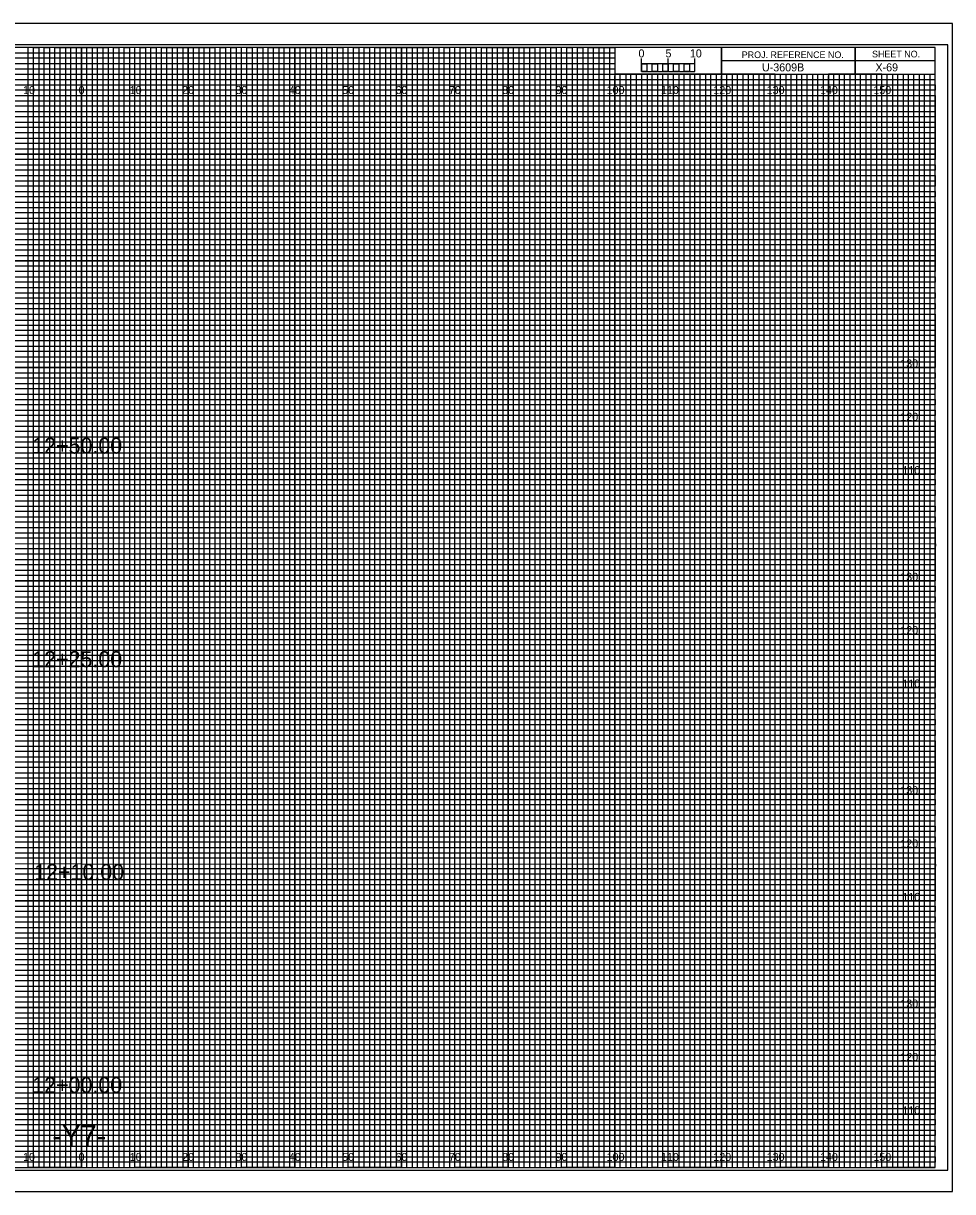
# Model space of a CAD drawing. Extents: x -13 to 323, y -5 to 215.
# Drawn here: x 149.1 to 323.3, y -4.5 to 214.5 of the extents above; entities that cross this region are included whole.
import ezdxf

# ---------------------------------------------------------------- set-up
doc = ezdxf.new("R2010")
doc.units = 0
for name, color, linetype in [('Prop XS Alignment Label', 7, 'Continuous'), ('Prop XS Bar Scale Labels', 7, 'Continuous'), ('Prop XS Elevation Labels', 7, 'Continuous'), ('Prop XS Offset Labels', 7, 'Continuous'), ('Prop XS Project Number', 7, 'Continuous'), ('Prop XS Sheet Number', 7, 'Continuous'), ('Prop XS Station Labels', 7, 'Continuous'), ('Sheet Cross Section CELL', 7, 'Continuous'), ('Sheet Cross Section Grid Major CELL', 7, 'Continuous'), ('Sheet Cross Section Grid Middle CELL', 7, 'Continuous'), ('Sheet Cross Section Grid Minor 1 CELL', 7, 'Continuous'), ('Sheet Cross Section Grid Minor 2 CELL', 7, 'Continuous'), ('Sheet Cross Section Scale CELL', 7, 'Continuous'), ('Sheet Cutting Line CELL', 7, 'Continuous'), ('Sheet DOT Grid CELL', 7, 'Continuous'), ('Sheet Plot Border Inside CELL', 7, 'Continuous'), ('Sheet Plot Border Outside CELL', 7, 'Continuous')]:
    doc.layers.add(name, color=color, linetype=linetype)

msp = doc.modelspace()

# ---------------------------------------------------------------- linework, layer by layer
at = {"layer": 'Sheet Cross Section CELL'}
for p, q in [((305, 210), (305, 205)), ((305, 205), (305, 210)), ((280, 207.5), (280, 205)), ((320, 207.49), (280, 207.49)), ((280, 205), (320, 205))]:
    msp.add_line(p, q, dxfattribs=at)
for points in [[(320, 210), (0, 210), (0, 0), (320, 0)], [(280, 210), (260, 210), (260, 205.03), (280, 205.03)], [(320, 210), (280, 210), (280, 205), (320, 205)]]:
    msp.add_lwpolyline(points, close=True, dxfattribs=at)
at = {"layer": 'Sheet Cross Section Grid Major CELL'}
for p, q in [((150, 210), (140, 210)), ((150, 0), (150, 210)), ((170, 210), (160, 210)), ((160, 210), (160, 0)), ((170, 0), (170, 210)), ((190, 210), (180, 210)), ((180, 210), (180, 0)), ((190, 0), (190, 210)), ((210, 210), (200, 210)), ((200, 210), (200, 0)), ((210, 0), (210, 210)), ((230, 210), (220, 210)), ((220, 210), (220, 0)), ((230, 0), (230, 210)), ((250, 210), (240, 210)), ((240, 210), (240, 0)), ((250, 0), (250, 210)), ((260, 210), (260, 0)), ((270, 0), (270, 205)), ((290, 205), (280, 205)), ((280, 205), (280, 0)), ((290, 0), (290, 205)), ((310, 205), (300, 205)), ((300, 205), (300, 0)), ((310, 0), (310, 205)), ((160, 0), (150, 0)), ((180, 0), (170, 0)), ((200, 0), (190, 0)), ((220, 0), (210, 0)), ((240, 0), (230, 0)), ((260, 0), (250, 0)), ((280, 0), (270, 0)), ((300, 0), (290, 0)), ((320, 0), (310, 0)), ((320, 0), (320, 0))]:
    msp.add_line(p, q, dxfattribs=at)
for points in [[(0, 200), (320, 200), (320, 190), (0, 190)], [(0, 180), (320, 180), (320, 170), (0, 170)], [(0, 160), (320, 160), (320, 150), (0, 150)], [(0, 140), (320, 140), (320, 130), (0, 130)], [(0, 120), (320, 120), (320, 110), (0, 110)], [(0, 100), (320, 100), (320, 90), (0, 90)], [(0, 80), (320, 80), (320, 70), (0, 70)], [(0, 60), (320, 60), (320, 50), (0, 50)], [(0, 40), (320, 40), (320, 30), (0, 30)], [(0, 20), (320, 20), (320, 10), (0, 10)]]:
    msp.add_lwpolyline(points, dxfattribs=at)
at = {"layer": 'Sheet Cross Section Grid Middle CELL'}
for points in [[(145, 0), (155, 0), (155, 210), (165, 210), (165, 0), (175, 0), (175, 210), (185, 210), (185, 0), (195, 0), (195, 210), (205, 210), (205, 0), (215, 0), (215, 210), (225, 210), (225, 0), (235, 0), (235, 210), (245, 210), (245, 0), (255, 0), (255, 210), (259.93, 210), (260, 210), (260, 205), (264.99, 205), (264.99, 0), (275, 0), (275, 205), (285, 205), (285, 0), (295, 0), (295, 205), (305, 205), (305, 0), (315, 0), (315, 205)], [(0, 205), (275, 205)], [(0, 185), (320, 185), (320, 195), (0, 195)], [(0, 165), (320, 165), (320, 175), (0, 175)], [(0, 145), (320, 145), (320, 155), (0, 155)], [(0, 125), (320, 125), (320, 135), (0, 135)], [(0, 105), (320, 105), (320, 115), (0, 115)], [(0, 85), (320, 85), (320, 95), (0, 95)], [(0, 65), (320, 65), (320, 75), (0, 75)], [(0, 45), (320, 45), (320, 55), (0, 55)], [(0, 25), (320, 25), (320, 35), (0, 35)], [(0, 5), (320, 5), (320, 15), (0, 15)]]:
    msp.add_lwpolyline(points, dxfattribs=at)
at = {"layer": 'Sheet Cross Section Grid Minor 1 CELL'}
for p, q in [((0, 209), (260, 209)), ((260, 209), (260, 207.98)), ((260, 207.98), (0, 207.98)), ((0, 207), (260, 207)), ((260, 205.89), (0, 205.89)), ((260, 207), (260, 205.89)), ((0, 204), (320, 204))]:
    msp.add_line(p, q, dxfattribs=at)
for points in [[(0, 203), (270, 203), (320, 203), (320, 202), (0, 202)], [(0, 201), (320, 201), (320, 199), (0, 199)], [(0, 198), (320, 198), (320, 197), (0, 196.98)], [(0, 196), (320, 196), (320, 194), (0, 194)], [(0, 193), (320, 193), (320, 192), (0, 192)], [(0, 191), (320, 191), (320, 189), (0, 189)], [(0, 188), (320, 188), (320, 187), (0, 187)], [(0, 186), (320, 186), (320, 184), (0, 184)], [(0, 183), (320, 183), (320, 182), (0, 182)], [(0, 181), (320, 181), (320, 179), (0, 179)], [(0, 178), (320, 178), (320, 177), (0, 177)], [(0, 176), (320, 176), (320, 173.95), (320, 173), (320, 172), (0, 172)], [(0, 174), (320, 174), (320, 173), (0, 173)], [(0, 171), (320, 171), (320, 169), (0, 169.03)], [(0, 169.03), (320, 169), (320, 168), (0, 168)], [(0, 167), (320, 167), (320, 166), (0, 166)], [(0, 164), (320, 164), (320, 163), (0, 163)], [(0, 162), (320, 162), (320, 161), (0, 161)], [(-0.07, 158.89), (320, 158.89), (320, 157.88), (-0.07, 157.88)], [(0, 157), (320, 157), (320, 156), (0, 156)], [(0, 154), (320, 154), (320, 153), (0, 153)], [(0, 152), (320, 152), (320, 151), (0, 151)], [(0, 149), (320, 149), (320, 148), (0, 148)], [(0, 147), (320, 147), (320, 146), (0, 146)], [(0, 144), (320, 144), (320, 143), (0, 143)], [(0, 142), (320, 142), (320, 141), (0, 141)], [(0, 139), (320, 139), (319.99, 137.98), (0, 138)], [(0, 137), (320, 137), (320, 136), (0, 136)], [(0, 134), (320, 134), (320, 133), (0, 133)], [(0, 132), (320, 132), (320, 131), (0, 131)], [(0, 129), (320, 129), (320, 128), (0, 128)], [(0, 127), (320, 127), (320, 126), (0, 126)], [(0, 124), (320, 124), (320, 123), (0, 123)], [(0, 122), (320, 122), (320, 121), (0, 121)], [(0, 119), (320, 119), (320, 118), (0, 118)], [(0, 116.99), (320.07, 116.91), (320, 116), (0, 116)], [(0, 114), (320, 114), (320, 113), (0, 113)], [(0, 112), (320, 112), (320, 111), (0, 111)], [(0, 109), (320, 109), (320, 108), (0, 108)], [(0, 107), (320, 107), (320, 106), (0, 106)], [(0, 104), (320, 104), (320, 103), (0, 103)], [(0, 102), (320, 102), (320, 101), (0, 101)], [(0, 99), (320, 99), (320, 98), (0, 98)], [(0, 97), (320, 97), (320, 96), (0, 96)], [(0, 94), (320, 94), (320, 93), (0, 93)], [(0, 92), (320, 92), (320, 91), (0, 91)], [(0, 89), (320, 89), (320, 88), (0, 88)], [(0, 87), (320, 87), (320, 86), (0, 86)], [(0, 84), (320, 84), (320, 83), (0, 83)], [(0, 82), (320, 82), (320, 81), (0, 81)], [(0, 79), (320, 79), (319.99, 77.98), (0, 78)], [(0, 77), (320, 77), (320, 76), (0, 76)], [(0, 74), (320, 74), (320, 73), (0, 73)], [(0, 72), (320, 72), (320, 71), (0, 71)], [(0, 69), (320, 69), (320, 68), (0, 68)], [(0, 67), (320, 67), (320, 66), (0, 66)], [(0, 64), (320, 64), (320, 63), (0, 63)], [(0, 62), (320, 62), (320, 61), (0, 61)], [(0, 59), (320, 59), (320, 58), (0, 58)], [(0, 56.99), (320.07, 56.91), (320, 56), (0, 56)], [(0, 54), (320, 54), (320, 53), (0, 53)], [(0, 52), (320, 52), (320, 51), (0, 51)], [(0, 49), (320, 49), (320, 48), (0, 48)], [(0, 47), (320, 47), (320, 46), (0, 46)], [(0, 44), (320, 44), (320, 43), (0, 43)], [(0, 42), (320, 42), (320, 41), (0, 41)], [(0, 39), (320, 39), (320, 38), (0, 38)], [(0, 37), (320, 37), (320, 36), (0, 36)], [(0, 34), (320, 34), (320, 33), (0, 33)], [(0, 32), (320, 32), (320, 31), (0, 31)], [(0, 29), (320, 29), (320, 28), (0, 28)], [(0, 27), (320, 27), (320, 26), (0, 26)], [(0, 24), (320, 24), (320, 23), (0, 23)], [(0, 22), (320, 22), (320, 21), (0, 21)], [(0, 19), (320, 19), (320, 18), (0, 18)], [(0, 17), (320, 17), (320, 16), (0, 16)], [(0, 14), (320, 14), (320, 13), (0, 13)], [(0, 12), (320, 12), (320, 11), (0, 11)], [(0, 9), (320, 9), (320, 8), (0, 8)], [(0, 7), (320, 7), (320, 6), (0, 6)], [(0, 4), (320, 4), (320, 3), (0, 3)], [(0, 2), (320, 2), (320, 1), (0, 1)]]:
    msp.add_lwpolyline(points, dxfattribs=at)
at = {"layer": 'Sheet Cross Section Grid Minor 2 CELL'}
for p, q in [((267, 205), (266.01, 205)), ((266.01, 205), (266.01, 0)), ((267, 0), (267, 205)), ((269, 205), (268, 205)), ((268, 205), (268, 0)), ((269, 0), (269, 205)), ((266.01, 0), (265, 0)), ((268, 0), (267, 0))]:
    msp.add_line(p, q, dxfattribs=at)
for points in [[(150, 0), (151, 0), (151, 210), (152, 210), (152, 0)], [(152, 0), (153, 0), (153, 210), (154, 210), (154, 0)], [(155, 0), (156, 0), (156, 210), (157, 210), (157, 0)], [(157, 0), (158, 0), (158, 210), (159, 210), (159, 0)], [(160, 0), (161, 0), (161, 210), (162, 210), (162, 0)], [(162, 0), (163, 0), (163, 210), (164, 210), (164, 0)], [(165, 0), (166, 0), (166, 210), (167, 210), (167, 0)], [(167, 0), (168, 0), (168, 210), (169, 210), (169, 0)], [(170, 0), (171, 0), (171, 210), (172, 210), (172, 0)], [(172, 0), (173, 0), (173, 210), (174, 210), (174, 0)], [(175, 0), (176, 0), (176, 210), (177, 210), (177, 0)], [(177, 0), (178, 0), (178, 210), (179, 210), (179, 0)], [(180, 0), (181, 0), (181, 210), (182, 210), (182, 0)], [(182, 0), (183, 0), (183, 210), (184, 210), (184, 0)], [(185, 0), (186, 0), (186, 210), (187, 210), (187, 0)], [(187, 0), (188, 0), (188, 210), (189, 210), (189, 0)], [(190, 0), (191, 0), (191, 210), (192, 210), (192, 0)], [(192, 0), (193, 0), (193, 210), (194, 210), (194, 0)], [(195, 0), (196, 0), (196, 210), (197, 210), (197, 0)], [(197, 0), (198, 0), (198, 210), (199, 210), (199, 0)], [(200, 0), (201, 0), (201, 210), (202, 210), (202, 0)], [(202, 0), (203, 0), (203, 210), (204, 210), (204, 0)], [(205, 0), (206, 0), (206, 210), (207, 210), (207, 0)], [(207, 0), (208, 0), (208, 210), (209, 210), (209, 0)], [(210, 0), (211, 0), (211, 210), (212, 210), (212, 0)], [(212, 0), (213, 0), (213, 210), (214, 210), (214, 0)], [(215, 0), (216, 0), (216, 210), (217, 210), (217, 0)], [(217, 0), (218, 0), (218, 210), (219, 210), (219, 0)], [(220, 0), (221, 0), (221, 210), (222, 210), (222, 0)], [(222, 0), (223, 0), (223, 210), (224, 210), (224, 0)], [(225, 0), (226, 0), (226, 210), (227, 210), (227, 0)], [(227, 0), (228, 0), (228, 210), (229, 210), (229, 0)], [(230, 0), (231, 0), (231, 210), (232, 210), (232, 0)], [(232, 0), (233, 0), (233, 210), (234, 210), (234, 0)], [(235, 0), (236, 0), (236, 210), (237, 210), (237, 0)], [(237, 0), (238, 0), (238, 210), (239, 210), (239, 0)], [(240, 0), (241, 0), (241, 210), (242, 210), (242, 0)], [(242, 0), (243, 0), (243, 210), (244, 210), (244, 0)], [(245, 0), (246, 0), (246, 210), (247, 210), (247, 0)], [(247, 0), (248, 0), (248, 210), (249, 210), (249, 0)], [(250, 0), (251, 0), (251, 210), (252, 210), (252, 0)], [(252, 0), (253, 0), (253, 210), (254, 210), (254, 0)], [(255, 0), (256, 0), (256, 210), (257, 210), (257, 0)], [(257, 0), (258, 0), (258, 210), (259, 210), (259, 0)], [(260, 0), (261, 0), (261, 205), (262.02, 205), (262.02, 0)], [(262, 0), (263, 0), (263, 205), (263.99, 205), (263.99, 0)], [(270, 0), (270.98, 0), (270.98, 205), (272, 205), (272, 0)], [(272, 0), (273, 0), (273, 205), (274.05, 205), (274.05, 0)], [(275, 0), (276, 0), (276, 205), (277, 205), (277, 0)], [(277, 0), (278, 0), (278, 205), (279, 205), (279, 0)], [(280, 0), (281, 0), (281, 205), (282, 205), (282, 0)], [(282, 0), (283, 0), (283, 205), (284, 205), (284, 0)], [(285, 0), (286, 0), (286, 205), (287, 205), (287, 0)], [(287, 0), (288, 0), (288, 205), (289, 205), (289, 0)], [(290, 0), (291, 0), (291, 205), (292, 205), (292, 0)], [(292, 0), (293, 0), (293, 205), (294, 205), (294, 0)], [(295, 0), (296, 0), (296, 205), (297, 205), (297, 0)], [(297, 0), (298, 0), (298, 205), (299, 205), (299, 0)], [(300, 0), (301, 0), (301, 205), (302, 205), (302, 0)], [(302, 0), (303, 0), (303, 205), (304, 205), (304, 0)], [(305, 0), (306, 0), (306, 205), (307, 205), (307, 0)], [(307, 0), (308, 0), (308, 205), (309, 205), (309, 0)], [(310, 0), (311, 0), (311, 205), (312, 205), (312, 0)], [(312, 0), (313, 0), (313, 205), (314, 205), (314, 0)], [(315, 0), (316, 0), (316, 205), (317, 205), (317, 0)], [(317, 0), (318, 0), (318, 205), (319, 205), (319, 0)]]:
    msp.add_lwpolyline(points, dxfattribs=at)
at = {"layer": 'Sheet Cross Section Scale CELL'}
for p, q in [((265, 205.49), (265, 207.9)), ((265, 206.9), (265, 207.9)), ((270, 205.49), (270, 207.9)), ((275, 205.49), (275, 207.9)), ((275, 206.9), (275, 207.9))]:
    msp.add_line(p, q, dxfattribs=at)
for points in [[(275, 206.9), (265, 206.9), (265, 205.49), (275, 205.49)], [(265, 206.9), (266, 206.9), (266, 205.49), (265, 205.49)], [(267, 206.9), (268, 206.9), (268, 205.49), (267, 205.49)], [(269, 206.9), (270, 206.9), (270, 205.49), (269, 205.49)], [(271, 206.9), (272, 206.9), (272, 205.49), (271, 205.49)], [(273, 206.9), (274, 206.9), (274, 205.49), (273, 205.49)]]:
    msp.add_lwpolyline(points, close=True, dxfattribs=at)
at = {"layer": 'Sheet Cutting Line CELL'}
for p, q in [((323.3, 214.5), (-13.4, 214.5)), ((-13.4, -4.5), (323.3, -4.5))]:
    msp.add_line(p, q, dxfattribs=at)
at = {"layer": 'Sheet DOT Grid CELL'}
for p, q in [((150, 0), (150, 210)), ((160, 0), (160, 210)), ((170, 0), (170, 210)), ((180, 0), (180, 210)), ((190, 0), (190, 210)), ((200, 0), (200, 210)), ((210, 0), (210, 210)), ((220, 0), (220, 210)), ((230, 0), (230, 210)), ((240, 0), (240, 210)), ((250, 0), (250, 210)), ((260, 0), (260, 204.69)), ((270, 0), (270, 204.69)), ((280, 0), (280, 204.69)), ((290, 0), (290, 204.69)), ((300, 0), (300, 204.69)), ((310, 0), (310, 204.69)), ((0, 200), (320, 200)), ((0, 190), (320, 190)), ((0, 180), (320, 180)), ((0, 170), (320, 170)), ((0, 160), (320, 160)), ((0, 150), (320, 150)), ((0, 140), (320, 140)), ((0, 130), (320, 130)), ((0, 120), (320, 120)), ((0, 110), (320, 110)), ((0, 100), (320, 100)), ((0, 90), (320, 90)), ((0, 80), (320, 80)), ((0, 70), (320, 70)), ((0, 60), (320, 60)), ((0, 50), (320, 50)), ((0, 40), (320, 40)), ((0, 30), (320, 30)), ((0, 20), (320, 20)), ((0, 10), (320, 10))]:
    msp.add_line(p, q, dxfattribs=at)
at = {"layer": 'Sheet Plot Border Inside CELL'}
msp.add_lwpolyline([(-10.8, -0.5), (322.4, -0.5), (322.4, 210.5), (-10.8, 210.5)], close=True, dxfattribs=at)
at = {"layer": 'Sheet Plot Border Outside CELL'}
msp.add_lwpolyline([(-13.4, -4.5), (323.3, -4.5), (323.3, 214.5), (-13.4, 214.5)], close=True, dxfattribs=at)

# ---------------------------------------------------------------- texts
at = {"layer": 'Prop XS Alignment Label'}
msp.add_text('-Y7-', height=4, dxfattribs=at).set_placement((154.52, 4))
at = {"layer": 'Prop XS Bar Scale Labels'}
for s, p in [('5', (269.47, 208.12)), ('10', (274.04, 208.12))]:
    msp.add_text(s, height=1.5, dxfattribs=at).set_placement(p)
at = {"layer": 'Prop XS Elevation Labels'}
for s, p in [('130', (313.49, 150)), ('120', (313.5, 140)), ('110', (313.88, 130)), ('130', (313.49, 110)), ('120', (313.5, 100)), ('110', (313.88, 90)), ('130', (313.49, 70)), ('120', (313.5, 60)), ('110', (313.88, 50)), ('130', (313.49, 30)), ('120', (313.5, 20)), ('110', (313.88, 10))]:
    msp.add_text(s, height=1.5, dxfattribs=at).set_placement(p)
at = {"layer": 'Prop XS Offset Labels'}
for s, p in [('10', (149.04, 201.25)), ('0', (159.45, 201.25)), ('0', (159.45, 201.25)), ('10', (169.04, 201.25)), ('20', (178.86, 201.25)), ('30', (188.86, 201.25)), ('40', (198.86, 201.25)), ('50', (208.86, 201.25)), ('60', (218.86, 201.25)), ('70', (228.86, 201.25)), ('80', (238.86, 201.25)), ('90', (248.86, 201.25)), ('100', (258.44, 201.25)), ('110', (268.62, 201.25)), ('120', (278.44, 201.25)), ('130', (288.44, 201.25)), ('140', (298.44, 201.25)), ('150', (308.44, 201.25)), ('10', (149.04, 1.25)), ('0', (159.45, 1.25)), ('0', (159.45, 1.25)), ('10', (169.04, 1.25)), ('20', (178.86, 1.25)), ('30', (188.86, 1.25)), ('40', (198.86, 1.25)), ('50', (208.86, 1.25)), ('60', (218.86, 1.25)), ('70', (228.86, 1.25)), ('80', (238.86, 1.25)), ('90', (248.86, 1.25)), ('100', (258.44, 1.25)), ('110', (268.62, 1.25)), ('120', (278.44, 1.25)), ('130', (288.44, 1.25)), ('140', (298.44, 1.25)), ('150', (308.44, 1.25))]:
    msp.add_text(s, height=1.5, dxfattribs=at).set_placement(p)
at = {"layer": 'Prop XS Project Number'}
msp.add_text('U-3609B', height=1.5, dxfattribs=at).set_placement((287.56, 205.5))
at = {"layer": 'Prop XS Sheet Number'}
msp.add_text('X-69', height=1.5, dxfattribs=at).set_placement((308.83, 205.5))
at = {"layer": 'Prop XS Station Labels'}
for s, p in [('12+50.00', (150.77, 133.84)), ('12+25.00', (150.77, 93.81)), ('12+10.00', (151.13, 53.92)), ('12+00.00', (150.77, 13.99))]:
    msp.add_text(s, height=3, dxfattribs=at).set_placement(p)
at = {"layer": 'Sheet Cross Section CELL'}
for s, p in [('PROJ. REFERENCE NO.', (283.77, 207.99)), ('SHEET NO.', (308.19, 208.12))]:
    msp.add_text(s, height=1.25, dxfattribs=at).set_placement(p)
at = {"layer": 'Sheet Cross Section Scale CELL'}
msp.add_text('0', height=1.5, dxfattribs=at).set_placement((264.41, 208.12))

doc.saveas('drawing.dxf')
